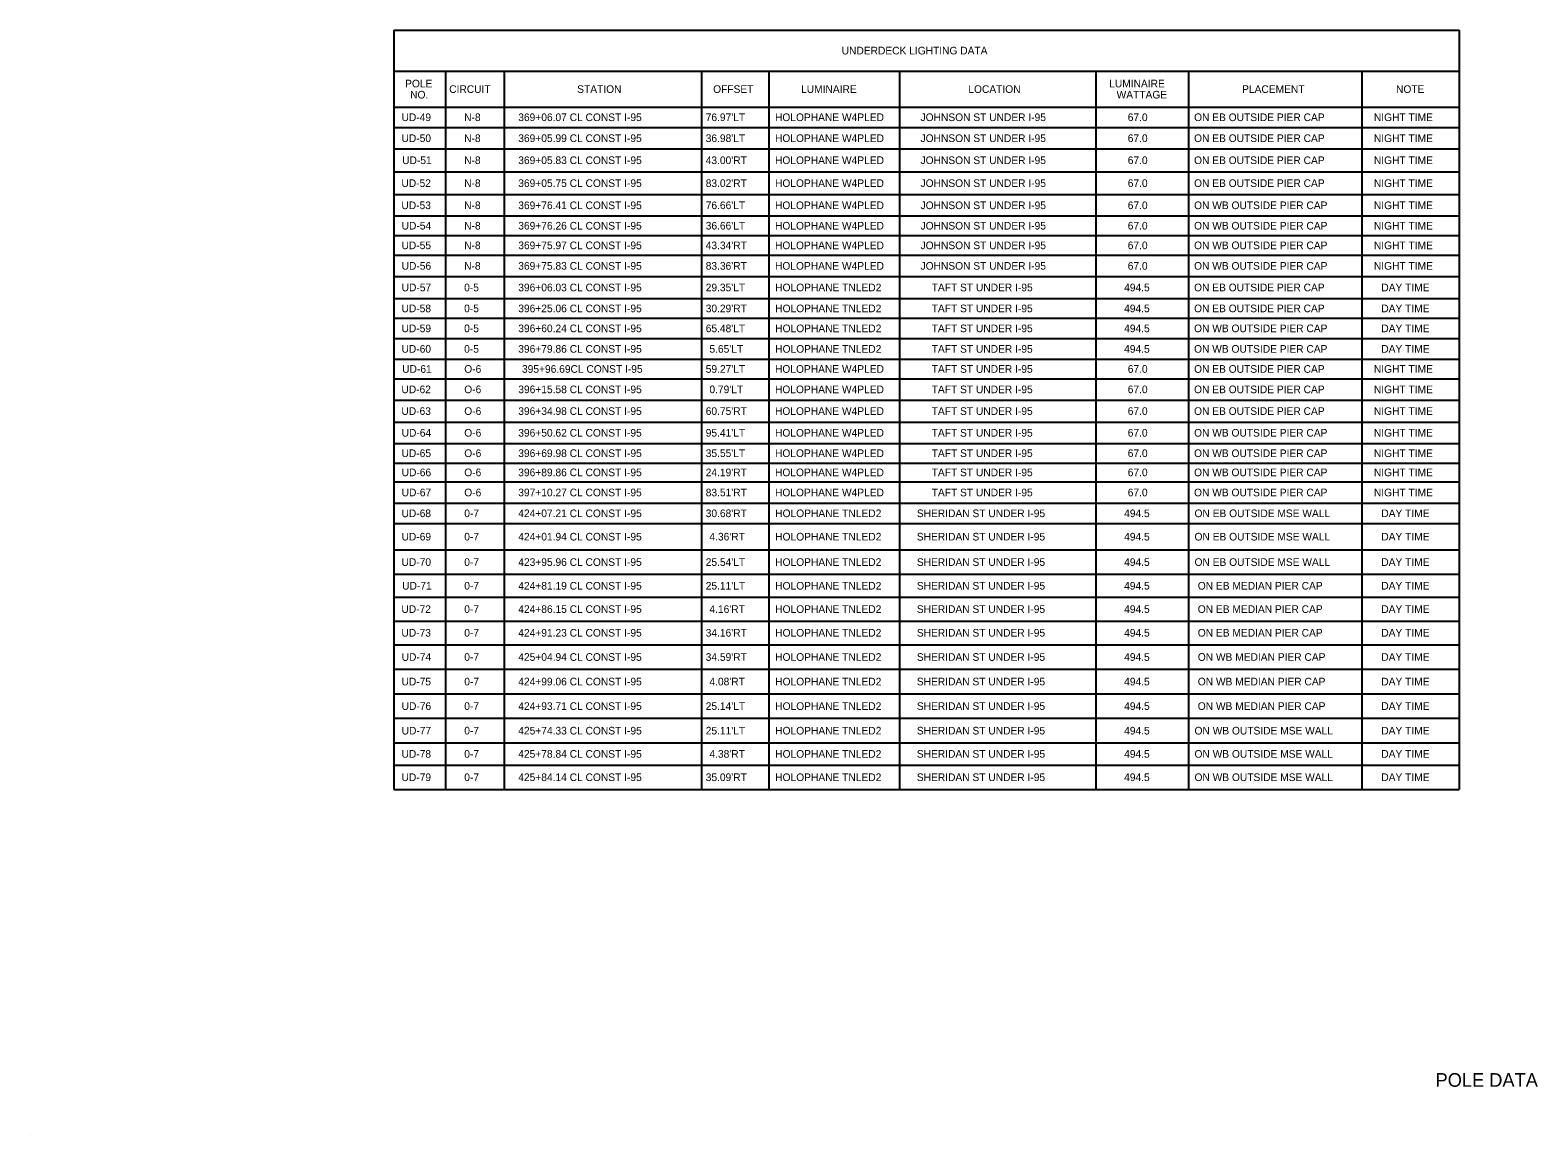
# Model space of a CAD drawing. Extents: x -816.7 to -727.6, y -2197.9 to -2187.8.
# Drawn here: x -761.72 to -747.9, y -2197.9 to -2187.77 of the extents above; entities that cross this region are included whole.
import ezdxf

# ---------------------------------------------------------------- set-up
doc = ezdxf.new("R2010")
doc.units = 0
for name, color, linetype in [('ClipBorder_dp', 7, 'Continuous'), ('MatchLines_dp', 7, 'Continuous'), ('NorthArw_dp', 7, 'Continuous'), ('Scale_dp', 7, 'Continuous'), ('TextLabel', 7, 'Continuous'), ('TextMisc', 7, 'Continuous')]:
    doc.layers.add(name, color=color, linetype=linetype)

msp = doc.modelspace()

# ---------------------------------------------------------------- linework, layer by layer
at = {"layer": 'MatchLines_dp'}
for p, q in [((-758.384, -2188.479), (-748.619, -2188.479)), ((-758.384, -2188.666), (-748.619, -2188.666)), ((-758.384, -2188.666), (-748.619, -2188.666)), ((-758.384, -2188.861), (-748.619, -2188.861)), ((-758.384, -2188.861), (-748.619, -2188.861)), ((-758.384, -2189.071), (-748.619, -2189.071)), ((-758.384, -2189.071), (-748.619, -2189.071)), ((-758.384, -2189.281), (-748.619, -2189.281)), ((-758.384, -2189.281), (-748.619, -2189.281)), ((-758.384, -2189.476), (-748.619, -2189.476)), ((-758.384, -2189.476), (-748.619, -2189.476)), ((-758.384, -2189.656), (-748.619, -2189.656)), ((-758.384, -2189.656), (-748.619, -2189.656)), ((-758.384, -2189.836), (-748.619, -2189.836)), ((-758.384, -2189.836), (-748.619, -2189.836)), ((-758.384, -2190.031), (-748.619, -2190.031)), ((-758.384, -2190.031), (-748.619, -2190.031)), ((-758.384, -2190.234), (-748.619, -2190.234)), ((-758.384, -2190.234), (-748.619, -2190.234)), ((-758.384, -2190.414), (-748.619, -2190.414)), ((-758.384, -2190.414), (-748.619, -2190.414)), ((-758.384, -2190.601), (-748.619, -2190.601)), ((-758.384, -2190.601), (-748.619, -2190.601)), ((-758.384, -2190.789), (-748.619, -2190.789)), ((-758.384, -2190.789), (-748.619, -2190.789)), ((-758.384, -2190.969), (-748.619, -2190.969)), ((-758.384, -2190.969), (-748.619, -2190.969)), ((-758.384, -2191.164), (-748.619, -2191.164)), ((-758.384, -2191.164), (-748.619, -2191.164)), ((-758.384, -2191.366), (-748.619, -2191.366)), ((-758.384, -2191.366), (-748.619, -2191.366)), ((-758.384, -2191.561), (-748.619, -2191.561)), ((-758.384, -2191.561), (-748.619, -2191.561)), ((-758.384, -2191.741), (-748.619, -2191.741)), ((-758.384, -2191.741), (-748.619, -2191.741)), ((-758.384, -2191.914), (-748.619, -2191.914)), ((-758.384, -2191.914), (-748.619, -2191.914)), ((-758.384, -2192.109), (-748.619, -2192.109)), ((-758.384, -2192.109), (-748.619, -2192.109)), ((-758.384, -2192.296), (-748.619, -2192.296)), ((-758.384, -2192.296), (-748.619, -2192.296)), ((-758.384, -2192.536), (-748.619, -2192.536)), ((-758.384, -2192.536), (-748.619, -2192.536)), ((-758.384, -2192.761), (-748.619, -2192.761)), ((-758.384, -2192.761), (-748.619, -2192.761)), ((-758.384, -2192.971), (-748.619, -2192.971)), ((-758.384, -2192.971), (-748.619, -2192.971)), ((-758.384, -2193.189), (-748.619, -2193.189)), ((-758.384, -2193.189), (-748.619, -2193.189)), ((-758.384, -2193.406), (-748.619, -2193.406)), ((-758.384, -2193.406), (-748.619, -2193.406)), ((-758.384, -2193.631), (-748.619, -2193.631)), ((-758.384, -2193.631), (-748.619, -2193.631)), ((-758.384, -2193.856), (-748.619, -2193.856)), ((-758.384, -2193.856), (-748.619, -2193.856)), ((-758.384, -2194.081), (-748.619, -2194.081)), ((-758.384, -2194.081), (-748.619, -2194.081)), ((-758.384, -2194.306), (-748.619, -2194.306)), ((-758.384, -2194.306), (-748.619, -2194.306)), ((-758.384, -2194.509), (-748.619, -2194.509)), ((-758.384, -2194.509), (-748.619, -2194.509))]:
    msp.add_line(p, q, dxfattribs=at)
at = {"layer": 'NorthArw_dp'}
for p, q in [((-758.384, -2187.774), (-748.619, -2187.774)), ((-758.384, -2187.774), (-758.384, -2194.734)), ((-748.619, -2187.774), (-748.619, -2194.734)), ((-758.384, -2188.149), (-748.619, -2188.149)), ((-758.384, -2188.149), (-748.619, -2188.149)), ((-749.512, -2188.149), (-749.512, -2194.734)), ((-749.512, -2188.479), (-749.512, -2194.734)), ((-758.384, -2194.734), (-748.619, -2194.734))]:
    msp.add_line(p, q, dxfattribs=at)
at = {"layer": 'Scale_dp'}
for p, q in [((-757.912, -2188.149), (-757.912, -2194.734)), ((-757.912, -2188.149), (-757.912, -2194.734)), ((-757.372, -2188.149), (-757.372, -2194.734)), ((-757.372, -2188.149), (-757.372, -2194.734)), ((-755.564, -2188.149), (-755.564, -2194.734)), ((-755.564, -2188.149), (-755.564, -2194.734)), ((-754.949, -2188.149), (-754.949, -2194.734)), ((-754.949, -2188.149), (-754.949, -2194.734)), ((-753.749, -2188.149), (-753.749, -2194.734)), ((-753.749, -2188.149), (-753.749, -2194.734)), ((-751.949, -2188.149), (-751.949, -2194.734)), ((-751.949, -2188.149), (-751.949, -2194.734)), ((-751.102, -2188.149), (-751.102, -2194.734)), ((-751.102, -2188.149), (-751.102, -2194.734)), ((-749.512, -2188.149), (-749.512, -2188.479)), ((-758.384, -2188.479), (-748.619, -2188.479))]:
    msp.add_line(p, q, dxfattribs=at)
at = {"layer": 'TextMisc'}
msp.add_line((-761.718, -2197.899), (-761.718, -2197.899), dxfattribs=at)

# ---------------------------------------------------------------- texts
at = {"layer": 'ClipBorder_dp'}
for s, p in [('UNDERDECK LIGHTING DATA', (-754.28, -2187.996)), ('POLE', (-758.281, -2188.298)), ('CIRCUIT', (-757.877, -2188.349)), ('STATION', (-756.704, -2188.349)), ('OFFSET', (-755.458, -2188.349)), ('LUMINAIRE', (-754.652, -2188.349)), ('LOCATION', (-753.119, -2188.349)), ('LUMINAIRE', (-751.828, -2188.298)), ('PLACEMENT', (-750.61, -2188.349)), ('NOTE', (-749.199, -2188.349)), ('NO.', (-758.235, -2188.4)), ('WATTAGE', (-751.76, -2188.4)), ('UD-49', (-758.314, -2188.607)), ('N-8', (-757.74, -2188.607)), ('369+06.07 CL CONST I-95', (-757.244, -2188.607)), ("76.97'LT", (-755.526, -2188.607)), ('HOLOPHANE W4PLED', (-754.891, -2188.607)), ('JOHNSON ST UNDER I-95', (-753.557, -2188.607)), ('67.0', (-751.658, -2188.607)), ('ON EB OUTSIDE PIER CAP', (-751.05, -2188.607)), ('NIGHT TIME', (-749.402, -2188.607)), ('UD-50', (-758.314, -2188.799)), ('N-8', (-757.74, -2188.799)), ('369+05.99 CL CONST I-95', (-757.244, -2188.799)), ("36.98'LT", (-755.526, -2188.799)), ('HOLOPHANE W4PLED', (-754.891, -2188.799)), ('JOHNSON ST UNDER I-95', (-753.557, -2188.799)), ('67.0', (-751.658, -2188.799)), ('ON EB OUTSIDE PIER CAP', (-751.05, -2188.799)), ('NIGHT TIME', (-749.402, -2188.799)), ('UD-51', (-758.308, -2189.001)), ('N-8', (-757.74, -2189.001)), ('369+05.83 CL CONST I-95', (-757.244, -2189.001)), ("43.00'RT", (-755.526, -2189.001)), ('HOLOPHANE W4PLED', (-754.891, -2189.001)), ('JOHNSON ST UNDER I-95', (-753.557, -2189.001)), ('67.0', (-751.658, -2189.001)), ('ON EB OUTSIDE PIER CAP', (-751.05, -2189.001)), ('NIGHT TIME', (-749.402, -2189.001)), ('UD-52', (-758.315, -2189.211)), ('N-8', (-757.74, -2189.211)), ('369+05.75 CL CONST I-95', (-757.244, -2189.211)), ("83.02'RT", (-755.526, -2189.211)), ('HOLOPHANE W4PLED', (-754.891, -2189.211)), ('JOHNSON ST UNDER I-95', (-753.557, -2189.211)), ('67.0', (-751.658, -2189.211)), ('ON EB OUTSIDE PIER CAP', (-751.05, -2189.211)), ('NIGHT TIME', (-749.402, -2189.211)), ('UD-53', (-758.315, -2189.414)), ('N-8', (-757.74, -2189.414)), ('369+76.41 CL CONST I-95', (-757.244, -2189.414)), ("76.66'LT", (-755.526, -2189.414)), ('HOLOPHANE W4PLED', (-754.891, -2189.414)), ('JOHNSON ST UNDER I-95', (-753.557, -2189.414)), ('67.0', (-751.658, -2189.414)), ('ON WB OUTSIDE PIER CAP', (-751.05, -2189.414)), ('NIGHT TIME', (-749.402, -2189.414)), ('UD-54', (-758.313, -2189.601)), ('N-8', (-757.74, -2189.601)), ('369+76.26 CL CONST I-95', (-757.244, -2189.601)), ("36.66'LT", (-755.526, -2189.601)), ('HOLOPHANE W4PLED', (-754.891, -2189.601)), ('JOHNSON ST UNDER I-95', (-753.557, -2189.601)), ('67.0', (-751.658, -2189.601)), ('ON WB OUTSIDE PIER CAP', (-751.05, -2189.601)), ('NIGHT TIME', (-749.402, -2189.601)), ('UD-55', (-758.314, -2189.781)), ('N-8', (-757.74, -2189.781)), ('369+75.97 CL CONST I-95', (-757.244, -2189.781)), ("43.34'RT", (-755.526, -2189.781)), ('HOLOPHANE W4PLED', (-754.891, -2189.781)), ('JOHNSON ST UNDER I-95', (-753.557, -2189.781)), ('67.0', (-751.658, -2189.781)), ('ON WB OUTSIDE PIER CAP', (-751.05, -2189.781)), ('NIGHT TIME', (-749.402, -2189.781)), ('UD-56', (-758.313, -2189.969)), ('N-8', (-757.74, -2189.969)), ('369+75.83 CL CONST I-95', (-757.244, -2189.969)), ("83.36'RT", (-755.526, -2189.969)), ('HOLOPHANE W4PLED', (-754.891, -2189.969)), ('JOHNSON ST UNDER I-95', (-753.557, -2189.969)), ('67.0', (-751.658, -2189.969)), ('ON WB OUTSIDE PIER CAP', (-751.05, -2189.969)), ('NIGHT TIME', (-749.402, -2189.969)), ('UD-57', (-758.313, -2190.167)), ('0-5', (-757.74, -2190.167)), ('396+06.03 CL CONST I-95', (-757.244, -2190.167)), ("29.35'LT", (-755.526, -2190.167)), ('HOLOPHANE TNLED2', (-754.889, -2190.167)), ('TAFT ST UNDER I-95', (-753.455, -2190.167)), ('494.5', (-751.691, -2190.167)), ('ON EB OUTSIDE PIER CAP', (-751.05, -2190.167)), ('DAY TIME', (-749.334, -2190.167)), ('UD-58', (-758.314, -2190.359)), ('0-5', (-757.74, -2190.359)), ('396+25.06 CL CONST I-95', (-757.244, -2190.359)), ("30.29'RT", (-755.526, -2190.359)), ('HOLOPHANE TNLED2', (-754.889, -2190.359)), ('TAFT ST UNDER I-95', (-753.455, -2190.359)), ('494.5', (-751.691, -2190.359)), ('ON EB OUTSIDE PIER CAP', (-751.05, -2190.359)), ('DAY TIME', (-749.334, -2190.359)), ('UD-59', (-758.314, -2190.542)), ('0-5', (-757.74, -2190.542)), ('396+60.24 CL CONST I-95', (-757.244, -2190.542)), ("65.48'LT", (-755.526, -2190.542)), ('HOLOPHANE TNLED2', (-754.889, -2190.542)), ('TAFT ST UNDER I-95', (-753.455, -2190.542)), ('494.5', (-751.691, -2190.542)), ('ON WB OUTSIDE PIER CAP', (-751.05, -2190.542)), ('DAY TIME', (-749.334, -2190.542)), ('UD-60', (-758.314, -2190.73)), ('0-5', (-757.74, -2190.73)), ('396+79.86 CL CONST I-95', (-757.244, -2190.73)), ("5.65'LT", (-755.492, -2190.73)), ('HOLOPHANE TNLED2', (-754.889, -2190.73)), ('TAFT ST UNDER I-95', (-753.455, -2190.73)), ('494.5', (-751.691, -2190.73)), ('ON WB OUTSIDE PIER CAP', (-751.05, -2190.73)), ('DAY TIME', (-749.334, -2190.73)), ('UD-61', (-758.308, -2190.914)), ('O-6', (-757.739, -2190.914)), ('395+96.69CL CONST I-95', (-757.21, -2190.914)), ("59.27'LT", (-755.526, -2190.914)), ('HOLOPHANE W4PLED', (-754.891, -2190.914)), ('TAFT ST UNDER I-95', (-753.455, -2190.914)), ('67.0', (-751.658, -2190.914)), ('ON EB OUTSIDE PIER CAP', (-751.05, -2190.914)), ('NIGHT TIME', (-749.402, -2190.914)), ('UD-62', (-758.315, -2191.101)), ('O-6', (-757.739, -2191.101)), ('396+15.58 CL CONST I-95', (-757.244, -2191.101)), ("0.79'LT", (-755.492, -2191.101)), ('HOLOPHANE W4PLED', (-754.891, -2191.101)), ('TAFT ST UNDER I-95', (-753.455, -2191.101)), ('67.0', (-751.658, -2191.101)), ('ON EB OUTSIDE PIER CAP', (-751.05, -2191.101)), ('NIGHT TIME', (-749.402, -2191.101)), ('UD-63', (-758.315, -2191.3)), ('O-6', (-757.739, -2191.3)), ('396+34.98 CL CONST I-95', (-757.244, -2191.3)), ("60.75'RT", (-755.526, -2191.3)), ('HOLOPHANE W4PLED', (-754.891, -2191.3)), ('TAFT ST UNDER I-95', (-753.455, -2191.3)), ('67.0', (-751.658, -2191.3)), ('ON EB OUTSIDE PIER CAP', (-751.05, -2191.3)), ('NIGHT TIME', (-749.402, -2191.3)), ('UD-64', (-758.313, -2191.499)), ('O-6', (-757.739, -2191.499)), ('396+50.62 CL CONST I-95', (-757.244, -2191.499)), ("95.41'LT", (-755.526, -2191.499)), ('HOLOPHANE W4PLED', (-754.891, -2191.499)), ('TAFT ST UNDER I-95', (-753.455, -2191.499)), ('67.0', (-751.658, -2191.499)), ('ON WB OUTSIDE PIER CAP', (-751.05, -2191.499)), ('NIGHT TIME', (-749.402, -2191.499)), ('UD-65', (-758.314, -2191.686)), ('O-6', (-757.739, -2191.686)), ('396+69.98 CL CONST I-95', (-757.244, -2191.686)), ("35.55'LT", (-755.526, -2191.686)), ('HOLOPHANE W4PLED', (-754.891, -2191.686)), ('TAFT ST UNDER I-95', (-753.455, -2191.686)), ('67.0', (-751.658, -2191.686)), ('ON WB OUTSIDE PIER CAP', (-751.05, -2191.686)), ('NIGHT TIME', (-749.402, -2191.686)), ('UD-66', (-758.313, -2191.862)), ('O-6', (-757.739, -2191.862)), ('396+89.86 CL CONST I-95', (-757.244, -2191.862)), ("24.19'RT", (-755.526, -2191.862)), ('HOLOPHANE W4PLED', (-754.891, -2191.862)), ('TAFT ST UNDER I-95', (-753.455, -2191.862)), ('67.0', (-751.658, -2191.862)), ('ON WB OUTSIDE PIER CAP', (-751.05, -2191.862)), ('NIGHT TIME', (-749.402, -2191.862)), ('UD-67', (-758.313, -2192.046)), ('O-6', (-757.739, -2192.046)), ('397+10.27 CL CONST I-95', (-757.244, -2192.046)), ("83.51'RT", (-755.526, -2192.046)), ('HOLOPHANE W4PLED', (-754.891, -2192.046)), ('TAFT ST UNDER I-95', (-753.455, -2192.046)), ('67.0', (-751.658, -2192.046)), ('ON WB OUTSIDE PIER CAP', (-751.05, -2192.046)), ('NIGHT TIME', (-749.402, -2192.046)), ('UD-68', (-758.314, -2192.237)), ('0-7', (-757.739, -2192.237)), ('424+07.21 CL CONST I-95', (-757.244, -2192.237)), ("30.68'RT", (-755.526, -2192.237)), ('HOLOPHANE TNLED2', (-754.889, -2192.237)), ('SHERIDAN ST UNDER I-95', (-753.591, -2192.237)), ('494.5', (-751.691, -2192.237)), ('ON EB OUTSIDE MSE WALL', (-751.046, -2192.237)), ('DAY TIME', (-749.334, -2192.237)), ('UD-69', (-758.314, -2192.451)), ('0-7', (-757.739, -2192.451)), ('424+01.94 CL CONST I-95', (-757.244, -2192.451)), ("4.36'RT", (-755.492, -2192.451)), ('HOLOPHANE TNLED2', (-754.889, -2192.451)), ('SHERIDAN ST UNDER I-95', (-753.591, -2192.451)), ('494.5', (-751.691, -2192.451)), ('ON EB OUTSIDE MSE WALL', (-751.046, -2192.451)), ('DAY TIME', (-749.334, -2192.451)), ('UD-70', (-758.314, -2192.684)), ('0-7', (-757.739, -2192.684)), ('423+95.96 CL CONST I-95', (-757.244, -2192.684)), ("25.54'LT", (-755.526, -2192.684)), ('HOLOPHANE TNLED2', (-754.889, -2192.684)), ('SHERIDAN ST UNDER I-95', (-753.591, -2192.684)), ('494.5', (-751.691, -2192.684)), ('ON EB OUTSIDE MSE WALL', (-751.046, -2192.684)), ('DAY TIME', (-749.334, -2192.684)), ('UD-71', (-758.308, -2192.901)), ('0-7', (-757.739, -2192.901)), ('424+81.19 CL CONST I-95', (-757.244, -2192.901)), ("25.11'LT", (-755.526, -2192.901)), ('HOLOPHANE TNLED2', (-754.889, -2192.901)), ('SHERIDAN ST UNDER I-95', (-753.591, -2192.901)), ('494.5', (-751.691, -2192.901)), ('ON EB MEDIAN PIER CAP', (-751.016, -2192.901)), ('DAY TIME', (-749.334, -2192.901)), ('UD-72', (-758.315, -2193.115)), ('0-7', (-757.739, -2193.115)), ('424+86.15 CL CONST I-95', (-757.244, -2193.115)), ("4.16'RT", (-755.492, -2193.115)), ('HOLOPHANE TNLED2', (-754.889, -2193.115)), ('SHERIDAN ST UNDER I-95', (-753.591, -2193.115)), ('494.5', (-751.691, -2193.115)), ('ON EB MEDIAN PIER CAP', (-751.016, -2193.115)), ('DAY TIME', (-749.334, -2193.115)), ('UD-73', (-758.315, -2193.332)), ('0-7', (-757.739, -2193.332)), ('424+91.23 CL CONST I-95', (-757.244, -2193.332)), ("34.16'RT", (-755.526, -2193.332)), ('HOLOPHANE TNLED2', (-754.889, -2193.332)), ('SHERIDAN ST UNDER I-95', (-753.591, -2193.332)), ('494.5', (-751.691, -2193.332)), ('ON EB MEDIAN PIER CAP', (-751.016, -2193.332)), ('DAY TIME', (-749.334, -2193.332)), ('UD-74', (-758.313, -2193.554)), ('0-7', (-757.739, -2193.554)), ('425+04.94 CL CONST I-95', (-757.244, -2193.554)), ("34.59'RT", (-755.526, -2193.554)), ('HOLOPHANE TNLED2', (-754.889, -2193.554)), ('SHERIDAN ST UNDER I-95', (-753.591, -2193.554)), ('494.5', (-751.691, -2193.554)), ('ON WB MEDIAN PIER CAP', (-751.016, -2193.554)), ('DAY TIME', (-749.334, -2193.554)), ('UD-75', (-758.314, -2193.779)), ('0-7', (-757.739, -2193.779)), ('424+99.06 CL CONST I-95', (-757.244, -2193.779)), ("4.08'RT", (-755.492, -2193.779)), ('HOLOPHANE TNLED2', (-754.889, -2193.779)), ('SHERIDAN ST UNDER I-95', (-753.591, -2193.779)), ('494.5', (-751.691, -2193.779)), ('ON WB MEDIAN PIER CAP', (-751.016, -2193.779)), ('DAY TIME', (-749.334, -2193.779)), ('UD-76', (-758.313, -2194.004)), ('0-7', (-757.739, -2194.004)), ('424+93.71 CL CONST I-95', (-757.244, -2194.004)), ("25.14'LT", (-755.526, -2194.004)), ('HOLOPHANE TNLED2', (-754.889, -2194.004)), ('SHERIDAN ST UNDER I-95', (-753.591, -2194.004)), ('494.5', (-751.691, -2194.004)), ('ON WB MEDIAN PIER CAP', (-751.016, -2194.004)), ('DAY TIME', (-749.334, -2194.004)), ('UD-77', (-758.313, -2194.229)), ('0-7', (-757.739, -2194.229)), ('425+74.33 CL CONST I-95', (-757.244, -2194.229)), ("25.11'LT", (-755.526, -2194.229)), ('HOLOPHANE TNLED2', (-754.889, -2194.229)), ('SHERIDAN ST UNDER I-95', (-753.591, -2194.229)), ('494.5', (-751.691, -2194.229)), ('ON WB OUTSIDE MSE WALL', (-751.046, -2194.229)), ('DAY TIME', (-749.334, -2194.229)), ('UD-78', (-758.314, -2194.442)), ('0-7', (-757.739, -2194.442)), ('425+78.84 CL CONST I-95', (-757.244, -2194.442)), ("4.38'RT", (-755.492, -2194.442)), ('HOLOPHANE TNLED2', (-754.889, -2194.442)), ('SHERIDAN ST UNDER I-95', (-753.591, -2194.442)), ('494.5', (-751.691, -2194.442)), ('ON WB OUTSIDE MSE WALL', (-751.046, -2194.442)), ('DAY TIME', (-749.334, -2194.442)), ('UD-79', (-758.314, -2194.656)), ('0-7', (-757.739, -2194.656)), ('425+84.14 CL CONST I-95', (-757.244, -2194.656)), ("35.09'RT", (-755.526, -2194.656)), ('HOLOPHANE TNLED2', (-754.889, -2194.656)), ('SHERIDAN ST UNDER I-95', (-753.591, -2194.656)), ('494.5', (-751.691, -2194.656)), ('ON WB OUTSIDE MSE WALL', (-751.046, -2194.656)), ('DAY TIME', (-749.334, -2194.656))]:
    msp.add_text(s, height=0.07, dxfattribs=at).set_placement(p)
at = {"layer": 'TextLabel'}
msp.add_text('POLE DATA', height=0.125, dxfattribs=at).set_placement((-748.837, -2197.458))

doc.saveas('drawing.dxf')
